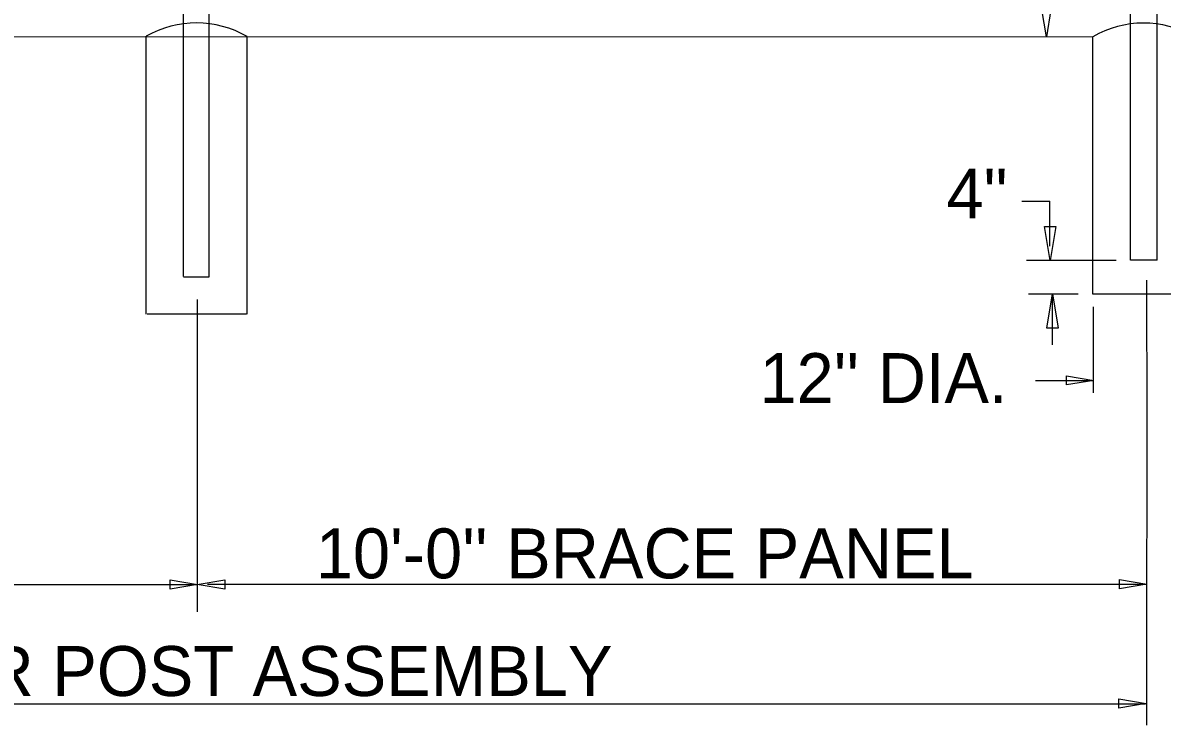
# Model space of a CAD drawing. Extents: x 0 to 2.85, y -0.1 to 1.83.
# Drawn here: x 2.2325 to 2.4608, y 0.6676 to 0.8083 of the extents above; entities that cross this region are included whole.
import ezdxf

# ---------------------------------------------------------------- set-up
doc = ezdxf.new("R2010")
doc.units = 0
for name, color, linetype in [('CT_CSHT_GeneralLabel', 7, 'Continuous'), ('CT_Dimensions', 7, 'Continuous'), ('sb_Chainlink Fence', 7, 'Continuous'), ('sb_Existing Concrete', 7, 'Continuous'), ('sb_Existing Structural Steel', 7, 'Continuous')]:
    doc.layers.add(name, color=color, linetype=linetype)

msp = doc.modelspace()

# ---------------------------------------------------------------- linework, layer by layer
at = {"layer": 'CT_Dimensions'}
for p, q in [((2.4326840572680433, 0.7725615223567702), (2.4382950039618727, 0.7725615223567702)), ((2.4382950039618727, 0.7635733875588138), (2.4382950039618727, 0.7725615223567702)), ((2.433621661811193, 0.7607772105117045), (2.451589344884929, 0.7607772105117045)), ((2.457769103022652, 0.7280344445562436), (2.4577317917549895, 0.7567665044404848)), ((2.433969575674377, 0.7539997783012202), (2.443957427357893, 0.7539997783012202)), ((2.438801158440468, 0.7438114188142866), (2.438801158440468, 0.7539840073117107)), ((2.267514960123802, 0.6903233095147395), (2.267514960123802, 0.7528803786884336)), ((2.447029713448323, 0.7341819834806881), (2.447029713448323, 0.7514371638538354)), ((2.4353976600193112, 0.7366869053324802), (2.4470306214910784, 0.7366869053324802)), ((2.4577386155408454, 0.6819635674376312), (2.457769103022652, 0.7280344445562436)), ((2.4577386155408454, 0.6676045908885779), (2.4577386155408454, 0.7008694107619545)), ((2.0731093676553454, 0.6957987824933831), (2.267473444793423, 0.6957987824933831)), ((2.2695329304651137, 0.6958615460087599), (2.4577386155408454, 0.6958615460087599)), ((2.077454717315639, 0.6719009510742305), (2.4574666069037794, 0.6719009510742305))]:
    msp.add_line(p, q, dxfattribs=at)
for points in [[(2.438492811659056, 0.8110029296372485), (2.4375767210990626, 0.8055063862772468), (2.436660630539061, 0.8110029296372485)], [(2.439504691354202, 0.7675232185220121), (2.438361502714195, 0.7606640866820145), (2.437218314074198, 0.7675232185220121)], [(2.4376630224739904, 0.7471429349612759), (2.4388062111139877, 0.7540020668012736), (2.439949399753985, 0.7471429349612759)], [(2.4415951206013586, 0.737602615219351), (2.447091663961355, 0.736686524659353), (2.4415951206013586, 0.735770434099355)], [(2.2620511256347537, 0.6967089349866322), (2.267547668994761, 0.6957928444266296), (2.2620511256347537, 0.694876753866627)], [(2.2729699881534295, 0.6948826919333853), (2.267473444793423, 0.6957987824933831), (2.2729699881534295, 0.6967148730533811)], [(2.4522420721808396, 0.6967776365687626), (2.4577386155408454, 0.6958615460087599), (2.4522420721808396, 0.694945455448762)], [(2.4520983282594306, 0.6728629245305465), (2.457594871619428, 0.6719468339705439), (2.4520983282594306, 0.6710307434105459)]]:
    msp.add_lwpolyline(points, close=True, dxfattribs=at)
at = {"layer": 'sb_Chainlink Fence'}
msp.add_line((1.8800525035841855, 0.8055800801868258), (2.446888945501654, 0.8055292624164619), dxfattribs=at)
at = {"layer": 'sb_Existing Concrete'}
for p, q in [((2.2572631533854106, 0.7499439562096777), (2.2572631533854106, 0.8056206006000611)), ((2.277472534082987, 0.7499215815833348), (2.277472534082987, 0.8055572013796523)), ((2.4468792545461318, 0.7539664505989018), (2.446888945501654, 0.8055292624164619)), ((2.4670894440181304, 0.7539664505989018), (2.4468792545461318, 0.7539664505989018)), ((2.257473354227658, 0.7499808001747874), (2.2773739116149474, 0.7499808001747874))]:
    msp.add_line(p, q, dxfattribs=at)
for centre, start, end in [((2.267312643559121, 0.7879930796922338), 59.952950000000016, 119.6875638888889), ((2.457048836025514, 0.7879651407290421), 60.31243611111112, 120.04705000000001)]:
    msp.add_arc(centre, 0.020290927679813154, start, end, dxfattribs=at)
at = {"layer": 'sb_Existing Structural Steel'}
for p, q in [((2.4544566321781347, 0.8080862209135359), (2.4544566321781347, 0.935975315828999)), ((2.4597995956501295, 0.8080681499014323), (2.4597995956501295, 0.935975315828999)), ((2.264688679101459, 0.8075347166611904), (2.2648827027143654, 0.9178714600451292)), ((2.269837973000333, 0.807634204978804), (2.270019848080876, 0.917607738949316)), ((2.4544566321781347, 0.760757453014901), (2.4544566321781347, 0.8080795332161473)), ((2.4597995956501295, 0.760757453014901), (2.4597995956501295, 0.8080795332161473)), ((2.264688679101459, 0.7574622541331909), (2.264688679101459, 0.8075347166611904)), ((2.269837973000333, 0.7573785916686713), (2.269837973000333, 0.807634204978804)), ((2.4597995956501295, 0.760757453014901), (2.4544566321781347, 0.760757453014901)), ((2.264691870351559, 0.7574242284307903), (2.2697890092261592, 0.7574242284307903)), ((2.4577386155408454, 0.6928938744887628), (2.4577386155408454, 0.7010567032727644))]:
    msp.add_line(p, q, dxfattribs=at)

# ---------------------------------------------------------------- texts
at = {"layer": 'CT_CSHT_GeneralLabel'}
msp.add_text('CORNER POST ASSEMBLY', height=0.01, dxfattribs=at).set_placement((2.176777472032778, 0.6734581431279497))
at = {"layer": 'CT_Dimensions'}
for s, p in [('4"', (2.417597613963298, 0.7691212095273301)), ("12'' DIA. ", (2.3800960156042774, 0.7321384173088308)), ("10'-0'' BRACE PANEL", (2.2912303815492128, 0.6970235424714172))]:
    msp.add_text(s, height=0.01, dxfattribs=at).set_placement(p)

doc.saveas('drawing.dxf')
